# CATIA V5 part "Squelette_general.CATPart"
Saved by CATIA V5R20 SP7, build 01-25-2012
Part number: Squelette_general
Publications: "Plan_ref", "AB"
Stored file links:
  F:\TRAV\IAO\Exercice IAO\Catia\Squelette_general.CATPart
  F:\TRAV\IAO\Exercice IAO\Catia\Squelette_regulateur.CATProduct
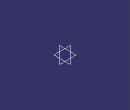
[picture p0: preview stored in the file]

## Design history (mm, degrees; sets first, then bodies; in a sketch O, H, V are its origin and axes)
Parameters
  AB = 70 mm
Body1 (main body)
  Plane1 "Plan_ref": type Offset, RefPlane yz-plane, Offset 0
